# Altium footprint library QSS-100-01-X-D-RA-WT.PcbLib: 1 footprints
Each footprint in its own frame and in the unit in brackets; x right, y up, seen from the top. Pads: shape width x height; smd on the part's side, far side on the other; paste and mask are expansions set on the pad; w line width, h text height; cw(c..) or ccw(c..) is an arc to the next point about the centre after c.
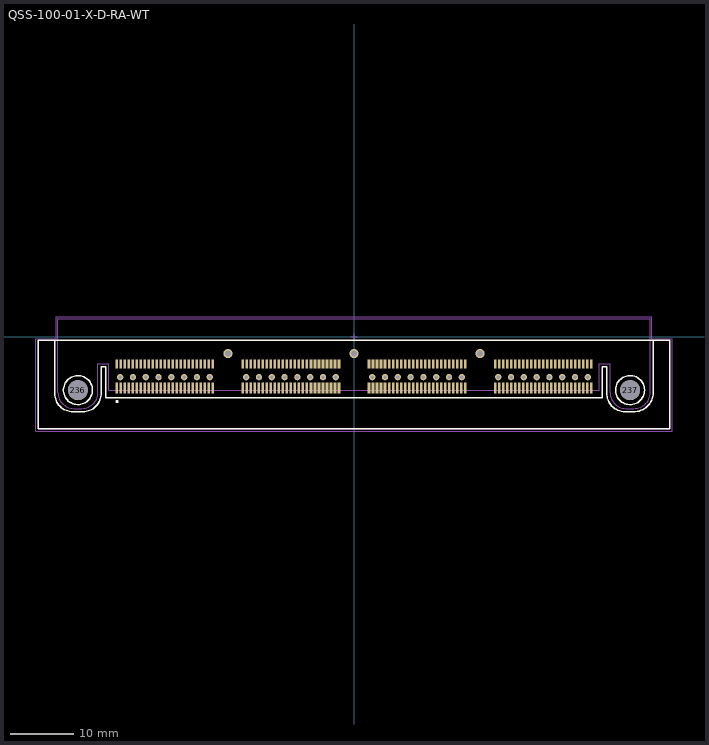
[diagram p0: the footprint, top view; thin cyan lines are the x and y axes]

## QSS-100-01-X-D-RA-WT [mm] "0.635mm pitch, 100 pin, high speed socket strip; r/a, w/weld tabs"
height 8.33
pads (237):
  rect 0.4x1.8 smd mask+0: 1(-37.624,-8.104) 3(-36.989,-8.104) 5(-36.354,-8.104) 7(-35.719,-8.104) 9(-35.084,-8.104) 11(-34.449,-8.104) 13(-33.814,-8.104) 15(-33.179,-8.104) 17(-32.544,-8.104) 19(-31.909,-8.104) 21(-31.274,-8.104) 23(-30.639,-8.104) 25(-30.004,-8.104) 27(-29.369,-8.104) 29(-28.734,-8.104) 31(-28.099,-8.104) 33(-27.464,-8.104) 35(-26.829,-8.104) 37(-26.194,-8.104) 39(-25.559,-8.104) 41(-24.924,-8.104) 43(-24.289,-8.104) 45(-23.654,-8.104) 47(-23.019,-8.104) 49(-22.384,-8.104) 51(-17.621,-8.104) 53(-16.986,-8.104) 55(-16.351,-8.104) 57(-15.716,-8.104) 59(-15.081,-8.104) 61(-14.446,-8.104) 63(-13.811,-8.104) 65(-13.176,-8.104) 67(-12.541,-8.104) 69(-11.906,-8.104) 71(-11.271,-8.104) 73(-10.636,-8.104) 75(-10.001,-8.104) 77(-9.366,-8.104) 79(-8.731,-8.104) 81(-8.096,-8.104) 83(-7.461,-8.104) 85(-6.826,-8.104) 87(-6.191,-8.104) 89(-5.556,-8.104) 91(-4.921,-8.104) 93(-4.286,-8.104) 95(-3.651,-8.104) 97(-3.016,-8.104) 99(-2.381,-8.104) 101(2.382,-8.104) 103(3.017,-8.104) 105(3.652,-8.104) 107(4.287,-8.104) 109(4.922,-8.104) 111(5.557,-8.104) 113(6.192,-8.104) 115(6.827,-8.104) 117(7.462,-8.104) 119(8.097,-8.104) 121(8.732,-8.104) 123(9.367,-8.104) 125(10.002,-8.104) 127(10.637,-8.104) 129(11.272,-8.104) 131(11.907,-8.104) 133(12.542,-8.104) 135(13.177,-8.104) 137(13.812,-8.104) 139(14.447,-8.104) 141(15.082,-8.104) 143(15.717,-8.104) 145(16.352,-8.104) 147(16.987,-8.104) 149(17.622,-8.104) 151(22.385,-8.104) 153(23.02,-8.104) 155(23.655,-8.104) 157(24.29,-8.104) 159(24.925,-8.104) 161(25.56,-8.104) 163(26.195,-8.104) 165(26.83,-8.104) 167(27.465,-8.104) 169(28.1,-8.104) 171(28.735,-8.104) 173(29.37,-8.104) 175(30.005,-8.104) 177(30.64,-8.104) 179(31.275,-8.104) 181(31.91,-8.104) 183(32.545,-8.104) 185(33.18,-8.104) 187(33.815,-8.104) 189(34.45,-8.104) 191(35.085,-8.104) 193(35.72,-8.104) 195(36.355,-8.104) 197(36.99,-8.104) 199(37.625,-8.104)
  rect 0.4x1.4 smd mask+0: 2(-37.624,-4.294) 4(-36.989,-4.294) 6(-36.354,-4.294) 8(-35.719,-4.294) 10(-35.084,-4.294) 12(-34.449,-4.294) 14(-33.814,-4.294) 16(-33.179,-4.294) 18(-32.544,-4.294) 20(-31.909,-4.294) 22(-31.274,-4.294) 24(-30.639,-4.294) 26(-30.004,-4.294) 28(-29.369,-4.294) 30(-28.734,-4.294) 32(-28.099,-4.294) 34(-27.464,-4.294) 36(-26.829,-4.294) 38(-26.194,-4.294) 40(-25.559,-4.294) 42(-24.924,-4.294) 44(-24.289,-4.294) 46(-23.654,-4.294) 48(-23.019,-4.294) 50(-22.384,-4.294) 52(-17.621,-4.294) 54(-16.986,-4.294) 56(-16.351,-4.294) 58(-15.716,-4.294) 60(-15.081,-4.294) 62(-14.446,-4.294) 64(-13.811,-4.294) 66(-13.176,-4.294) 68(-12.541,-4.294) 70(-11.906,-4.294) 72(-11.271,-4.294) 74(-10.636,-4.294) 76(-10.001,-4.294) 78(-9.366,-4.294) 80(-8.731,-4.294) 82(-8.096,-4.294) 84(-7.461,-4.294) 86(-6.826,-4.294) 88(-6.191,-4.294) 90(-5.556,-4.294) 92(-4.921,-4.294) 94(-4.286,-4.294) 96(-3.651,-4.294) 98(-3.016,-4.294) 100(-2.381,-4.294) 102(2.382,-4.294) 104(3.017,-4.294) 106(3.652,-4.294) 108(4.287,-4.294) 110(4.922,-4.294) 112(5.557,-4.294) 114(6.192,-4.294) 116(6.827,-4.294) 118(7.462,-4.294) 120(8.097,-4.294) 122(8.732,-4.294) 124(9.367,-4.294) 126(10.002,-4.294) 128(10.637,-4.294) 130(11.272,-4.294) 132(11.907,-4.294) 134(12.542,-4.294) 136(13.177,-4.294) 138(13.812,-4.294) 140(14.447,-4.294) 142(15.082,-4.294) 144(15.717,-4.294) 146(16.352,-4.294) 148(16.987,-4.294) 150(17.622,-4.294) 152(22.385,-4.294) 154(23.02,-4.294) 156(23.655,-4.294) 158(24.29,-4.294) 160(24.925,-4.294) 162(25.56,-4.294) 164(26.195,-4.294) 166(26.83,-4.294) 168(27.465,-4.294) 170(28.1,-4.294) 172(28.735,-4.294) 174(29.37,-4.294) 176(30.005,-4.294) 178(30.64,-4.294) 180(31.275,-4.294) 182(31.91,-4.294) 184(32.545,-4.294) 186(33.18,-4.294) 188(33.815,-4.294) 190(34.45,-4.294) 192(35.085,-4.294) 194(35.72,-4.294) 196(36.355,-4.294) 198(36.99,-4.294) 200(37.625,-4.294)
  round 1 hole 0.55 mask+0: 201(-37.116,-6.377) 202(-35.084,-6.377) 203(-33.052,-6.377) 204(-31.02,-6.377) 205(-28.988,-6.377) 206(-26.956,-6.377) 207(-24.924,-6.377) 208(-22.892,-6.377) 209(-17.113,-6.377) 210(-15.081,-6.377) 211(-13.049,-6.377) 212(-11.017,-6.377) 213(-8.985,-6.377) 214(-6.953,-6.377) 215(-4.921,-6.377) 216(-2.889,-6.377) 217(2.89,-6.377) 218(4.922,-6.377) 219(6.954,-6.377) 220(8.986,-6.377) 221(11.018,-6.377) 222(13.05,-6.377) 223(15.082,-6.377) 224(17.114,-6.377) 225(22.893,-6.377) 226(24.925,-6.377) 227(26.957,-6.377) 228(28.989,-6.377) 229(31.021,-6.377) 230(33.053,-6.377) 231(35.085,-6.377) 232(37.117,-6.377)
  round 1.45 hole 1 mask+0: 233(-20.003,-2.63) 234(0,-2.63) 235(20.003,-2.63)
  round 3.175 hole 3.175 unplated mask+0: 236(-43.816,-8.434) 237(43.816,-8.434)
Top Overlay:
  circle w0.2: c43.81,-8.43 r2.3
  circle w0.25: c-37.6,-10.25 r0.125
  circle w0.2: c-43.816,-8.43 r2.3
  lines w0.2: 40.114,-8.918 40.114,-4.75 39.402,-4.75 39.402,-9.652 -39.402,-9.652 -39.402,-4.724 -40.114,-4.724 -40.114,-8.915 cw(c-43.06,-8.915) -43.06,-11.862 -44.597,-11.862 cw(c-44.597,-8.979) -47.48,-8.979 -47.48,-0.5 47.48,-0.5 47.48,-8.873 ; 40.114,-8.917 ccw(c43.022,-8.953) 42.987,-11.862 ; 42.988,-11.862 44.345,-11.862 ; 44.343,-11.862 ccw(c44.418,-8.8) 47.479,-8.875 ; -50.15,-14.6 -50.15,-0.5 50.15,-0.5 50.15,-14.6 -50.15,-14.6
Mechanical 13:
  lines w0.1: 47.031,-8.815 cw(c44.465,-8.788) 44.406,-11.354 43.136,-11.354 cw(c43.158,-8.836) 40.641,-8.814 40.641,-4.242 38.894,-4.242 38.894,-8.433 -38.894,-8.433 -38.894,-4.242 -40.641,-4.242 -40.641,-8.814 cw(c-43.181,-8.814) -43.181,-11.354 -44.451,-11.354 cw(c-44.45,-8.814) -46.991,-8.814 -46.991,2.87 47.031,2.87 47.031,-8.814
  text ".Designator" at 0,0 h1.52
  text "J1" at -44.039,-3.45 h0.75
Mechanical 15:
  lines w0.001: -50.15,-14.6 50.15,-14.6 50.15,-0.5 -50.15,-0.5 -50.15,-14.6
  lines w0.05: -0.5,0 0.5,0 ; 0,-0.5 0,0.5 ; -50.5,-15 -50.5,-0.25 -47.25,-0.25 -47.25,3.25 47.25,3.25 47.25,-0.25 50.5,-0.25 50.5,-15 -50.5,-15
Drill Drawing:
  lines w0.01: -50.5,-0.13 50.5,-0.13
